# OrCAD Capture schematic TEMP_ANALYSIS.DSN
size A
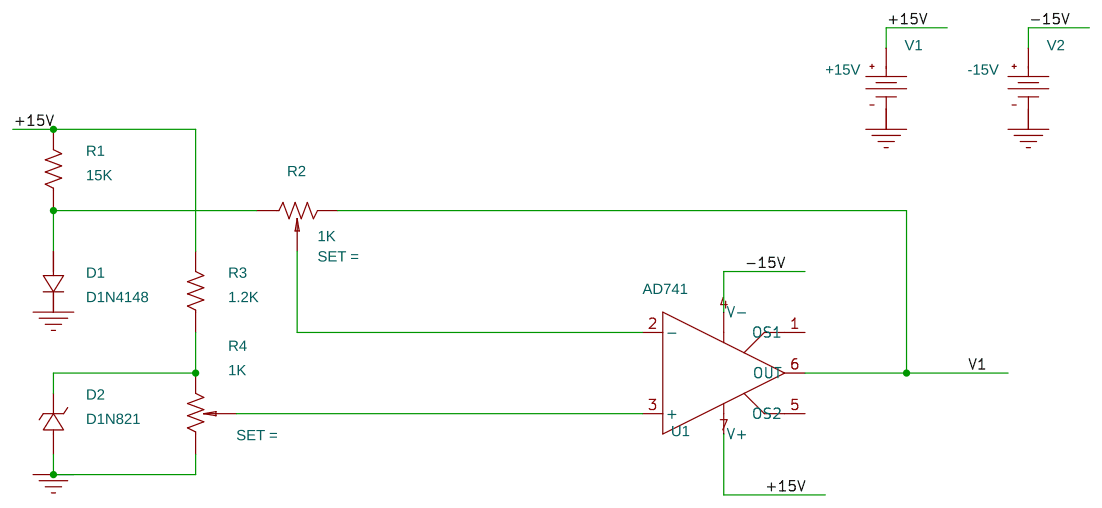
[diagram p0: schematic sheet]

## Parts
D1  D1N4148  [dax2do35]
D2  D1N821  [dax1do204ah]
R1  15K  [RC05]
R2  1K  [VRES10]
R3  1.2K  [RC05]
R4  1K  [VRES10]
U1  AD741  [DIP1008W300L450]
V1  VDC
V2  VDC

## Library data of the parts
D1 = D1N4148
D2 = D1N821
R1 R3 = R
R2 R4 = POT
U1 = AD741
V1 = VDC: DC: +15V
V2 = VDC: DC: -15V

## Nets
+15V: R1.2 R3.2 U1.7(V+) V1.0(+)
-15V: U1.4(V-) V2.0(+)
V1: R2.3(2) U1.6(OUT)
0: D1.2 D2.1 R4.1 V1.1(-) V2.1(-)
N00319: D1.1 R1.1 R2.1
N00364: D2.2 R3.1 R4.3(2)
N00388: R2.2(t) U1.2(-)
N00406: R4.2(t) U1.3(+)

Not connected (* = marked no-connect by the designer): U1 1(OS1) 5(OS2)
